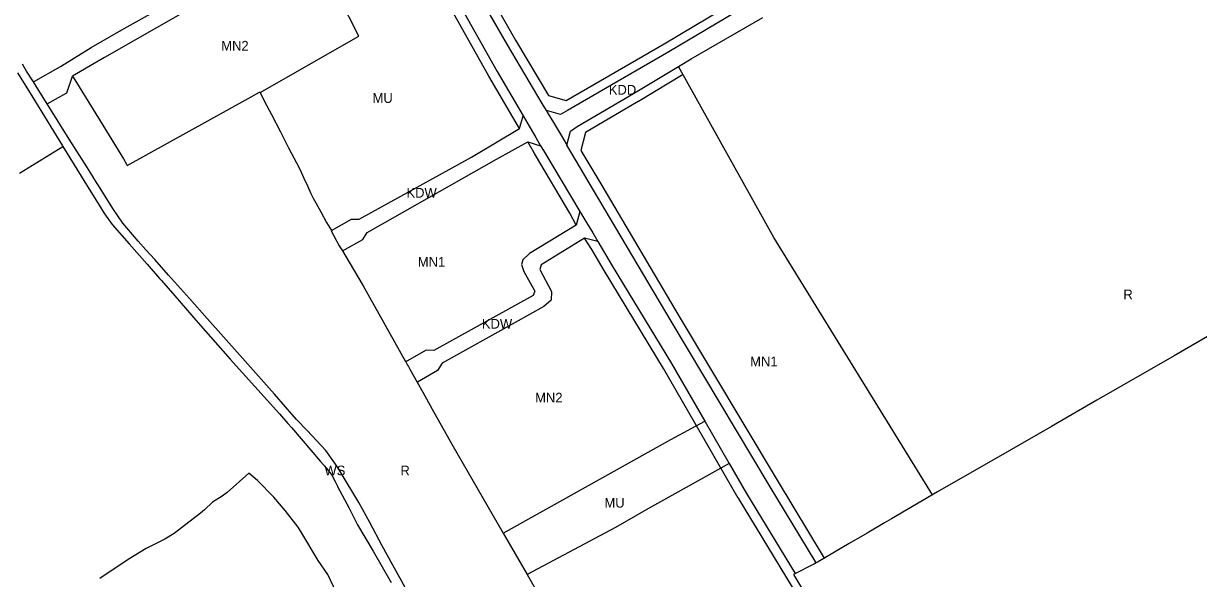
# Model space of a CAD drawing. Extents: x 7435758 to 7439981, y 5550649 to 5554049.
# Drawn here: x 7437442 to 7438071, y 5551241 to 5551538 of the extents above; entities that cross this region are included whole.
import ezdxf

# ---------------------------------------------------------------- set-up
doc = ezdxf.new("R2010")
doc.units = 0
for name, color, linetype in [('#Ruszcza', 7, 'Continuous'), ('linie_rozgraniczające', 7, 'Continuous'), ('linie_zabudowy_nieprzekraczalne', 7, 'Continuous'), ('oznaczenia_przeznaczen', 7, 'Continuous')]:
    doc.layers.add(name, color=color, linetype=linetype)

msp = doc.modelspace()

# ---------------------------------------------------------------- linework, layer by layer
at = {"layer": '#Ruszcza'}
for points in [[(7438090.73, 5551379.13), (7438058.41, 5551360.45), (7438017.13, 5551336.64), (7437992.72, 5551322.56), (7437970.1, 5551309.51), (7437931.84, 5551287.53), (7437907.14, 5551273.07), (7437903.34, 5551270.84), (7437894.03, 5551265.44), (7437884.44, 5551259.9), (7437867.86, 5551250.06), (7437866.85, 5551249.51), (7437865.88, 5551248.94), (7437854.67, 5551243.25), (7437871.03, 5551215.66)], [(7437609.91, 5551233.78), (7437605.33, 5551243.14), (7437600.15, 5551250.74), (7437591.49, 5551265.36), (7437589.42, 5551268.58), (7437582.59, 5551277.49), (7437576.53, 5551284.57), (7437567.78, 5551293.59), (7437563.17, 5551297.51), (7437551.5, 5551287.21), (7437548.85, 5551285.16), (7437543.57, 5551282.06), (7437539.33, 5551277.86), (7437537.17, 5551276.09), (7437523.11, 5551265.13), (7437518.16, 5551262.23), (7437508.19, 5551257.18), (7437498.58, 5551251.32), (7437483.4, 5551241.05)]]:
    msp.add_lwpolyline(points, dxfattribs=at)
at = {"layer": 'linie_rozgraniczające'}
for p, q in [((7437701.57, 5551526.92), (7437651.34, 5551614.85)), ((7437496.28, 5551535.7), (7437578.11, 5551581.52)), ((7437622, 5551531.63), (7437609.34, 5551556.45)), ((7437670.53, 5551558.04), (7437695.96, 5551512.69)), ((7437541.41, 5551552.18), (7437485.75, 5551520.23)), ((7437828.25, 5551547.15), (7437787.93, 5551523.28)), ((7437799.93, 5551519.4), (7437838.31, 5551541.54)), ((7437478.6, 5551525.54), (7437496.28, 5551535.7)), ((7437569.07, 5551501.4), (7437622, 5551531.63)), ((7437464.55, 5551516.73), (7437478.6, 5551525.54)), ((7437720.17, 5551495.53), (7437701.57, 5551526.92)), ((7437482.38, 5551518.3), (7437468.63, 5551510.25)), ((7437485.75, 5551520.23), (7437482.38, 5551518.3)), ((7437787.93, 5551523.28), (7437733.69, 5551491.76)), ((7437793.08, 5551515.29), (7437799.93, 5551519.4)), ((7437439.31, 5551511.91), (7437443.68, 5551504.82)), ((7437444.13, 5551512.88), (7437442, 5551516.56)), ((7437447.8, 5551507.06), (7437444.13, 5551512.88)), ((7437447.87, 5551507.1), (7437462.3, 5551515.43)), ((7437462.3, 5551515.43), (7437464.27, 5551516.57)), ((7437464.27, 5551516.57), (7437464.55, 5551516.73)), ((7437695.96, 5551512.69), (7437709.87, 5551489)), ((7437769.04, 5551500.85), (7437793.08, 5551515.29)), ((7437844.14, 5551423.82), (7437793.08, 5551515.29)), ((7437447.8, 5551507.06), (7437447.87, 5551507.1)), ((7437452.15, 5551500.11), (7437447.8, 5551507.06)), ((7437465.61, 5551501.21), (7437468.63, 5551510.25)), ((7437468.63, 5551510.25), (7437469.93, 5551508.17)), ((7437469.93, 5551508.17), (7437469.93, 5551508.16)), ((7437469.93, 5551508.16), (7437483.59, 5551486.32)), ((7437443.68, 5551504.82), (7437448.84, 5551496.44)), ((7437452.15, 5551500.1), (7437452.15, 5551500.11)), ((7437455.1, 5551495.38), (7437452.15, 5551500.1)), ((7437455.1, 5551495.38), (7437465.61, 5551501.21)), ((7437562.78, 5551498.27), (7437568.83, 5551501.62)), ((7437568.83, 5551501.62), (7437568.93, 5551501.68)), ((7437568.93, 5551501.68), (7437568.96, 5551501.62)), ((7437568.96, 5551501.62), (7437569.07, 5551501.4)), ((7437569.07, 5551501.4), (7437571.51, 5551496.7)), ((7437738.9, 5551483.22), (7437769.04, 5551500.85)), ((7437448.84, 5551496.44), (7437448.85, 5551496.43)), ((7437448.85, 5551496.43), (7437463.41, 5551472.81)), ((7437467.84, 5551475.04), (7437455.1, 5551495.38)), ((7437498, 5551462.41), (7437562.78, 5551498.27)), ((7437571.51, 5551496.7), (7437575.21, 5551489.57)), ((7437722.37, 5551491.81), (7437720.17, 5551495.53)), ((7437575.21, 5551489.57), (7437580.02, 5551480.3)), ((7437708.02, 5551482.1), (7437709.87, 5551489)), ((7437709.87, 5551489), (7437712.39, 5551484.71)), ((7437722.37, 5551491.81), (7437722.89, 5551490.94)), ((7437729.92, 5551489.6), (7437722.37, 5551491.81)), ((7437722.89, 5551490.94), (7437725.29, 5551486.88)), ((7437725.29, 5551486.88), (7437725.68, 5551486.23)), ((7437733.69, 5551491.76), (7437729.92, 5551489.6)), ((7437483.59, 5551486.32), (7437495.92, 5551465.91)), ((7437682.35, 5551466.73), (7437708.02, 5551482.1)), ((7437712.39, 5551484.71), (7437716.73, 5551477.32)), ((7437725.68, 5551486.23), (7437730.4, 5551478.26)), ((7437733.34, 5551473.3), (7437735.26, 5551480.73)), ((7437735.26, 5551480.73), (7437738.9, 5551483.22)), ((7437468.5, 5551473.97), (7437467.84, 5551475.04)), ((7437580.02, 5551480.3), (7437584.4, 5551471.85)), ((7437695.61, 5551465.77), (7437712.43, 5551474.97)), ((7437712.43, 5551474.97), (7437719.31, 5551472.93)), ((7437716.73, 5551477.32), (7437719.31, 5551472.93)), ((7437730.4, 5551478.26), (7437732.96, 5551473.93)), ((7437440.33, 5551458.26), (7437463.55, 5551472.55)), ((7437463.41, 5551472.81), (7437463.56, 5551472.56)), ((7437463.55, 5551472.55), (7437463.56, 5551472.56)), ((7437463.56, 5551472.56), (7437477.15, 5551450.5)), ((7437477.53, 5551459.57), (7437468.5, 5551473.97)), ((7437584.4, 5551471.85), (7437588.57, 5551463.81)), ((7437719.31, 5551472.93), (7437720.79, 5551470.41)), ((7437720.79, 5551470.41), (7437740.34, 5551437.61)), ((7437732.96, 5551473.93), (7437733.34, 5551473.3)), ((7437735.5, 5551469.63), (7437733.34, 5551473.3)), ((7437747.69, 5551449.05), (7437735.5, 5551469.63)), ((7437495.92, 5551465.91), (7437497.67, 5551462.96)), ((7437497.67, 5551462.96), (7437498, 5551462.41)), ((7437588.57, 5551463.81), (7437590.39, 5551460.3)), ((7437622.11, 5551433.49), (7437682.35, 5551466.73)), ((7437628.08, 5551427.37), (7437695.61, 5551465.77)), ((7437481.55, 5551453.16), (7437477.53, 5551459.57)), ((7437590.39, 5551460.3), (7437592.55, 5551455.6)), ((7437592.55, 5551455.6), (7437594.43, 5551451.51)), ((7437477.15, 5551450.5), (7437482.92, 5551441.05)), ((7437482.57, 5551451.53), (7437481.55, 5551453.16)), ((7437490.26, 5551439.33), (7437482.57, 5551451.53)), ((7437594.43, 5551451.51), (7437596.37, 5551447.27)), ((7437789.1, 5551378.96), (7437747.69, 5551449.05)), ((7437596.37, 5551447.27), (7437597.49, 5551444.84)), ((7437597.49, 5551444.84), (7437598.94, 5551442.27)), ((7437482.92, 5551441.05), (7437485.77, 5551436.37)), ((7437485.77, 5551436.37), (7437490, 5551430.8)), ((7437495.56, 5551431.41), (7437490.26, 5551439.33)), ((7437598.94, 5551442.27), (7437601.67, 5551437.43)), ((7437601.67, 5551437.43), (7437604.73, 5551431.76)), ((7437740.34, 5551437.61), (7437738.36, 5551430.44)), ((7437740.34, 5551437.61), (7437742.94, 5551433.25)), ((7437490, 5551430.8), (7437499.01, 5551420.3)), ((7437497.7, 5551428.94), (7437495.56, 5551431.41)), ((7437604.73, 5551431.76), (7437607.27, 5551427.5)), ((7437607.27, 5551427.5), (7437618.01, 5551433.54)), ((7437618.01, 5551433.54), (7437622.11, 5551433.49)), ((7437738.36, 5551430.44), (7437713.37, 5551415.12)), ((7437742.94, 5551433.25), (7437747.16, 5551426.17)), ((7437503.92, 5551421.75), (7437497.7, 5551428.94)), ((7437607.27, 5551427.5), (7437607.08, 5551427.39)), ((7437607.08, 5551427.39), (7437608.34, 5551425.05)), ((7437608.34, 5551425.05), (7437611.46, 5551419.38)), ((7437624.13, 5551422.64), (7437626.4, 5551426.47)), ((7437626.4, 5551426.47), (7437628.08, 5551427.37)), ((7437747.16, 5551426.17), (7437749.88, 5551421.6)), ((7437929.1, 5551285.93), (7437844.14, 5551423.82)), ((7437499.01, 5551420.3), (7437508.62, 5551409.43)), ((7437507.97, 5551417.23), (7437503.92, 5551421.75)), ((7437611.46, 5551419.38), (7437613.22, 5551416.56)), ((7437613.29, 5551416.6), (7437624.13, 5551422.64)), ((7437742.73, 5551423.43), (7437719.6, 5551409.14)), ((7437749.88, 5551421.6), (7437742.73, 5551423.43)), ((7437749.88, 5551421.6), (7437757.63, 5551408.61)), ((7437512.75, 5551411.9), (7437507.97, 5551417.23)), ((7437520.15, 5551403.52), (7437512.75, 5551411.9)), ((7437613.22, 5551416.56), (7437613.29, 5551416.6)), ((7437613.22, 5551416.56), (7437614.54, 5551414.45)), ((7437614.54, 5551414.45), (7437624.22, 5551397.83)), ((7437709.77, 5551411.73), (7437709.12, 5551409.21)), ((7437713.37, 5551415.12), (7437709.77, 5551411.73)), ((7437508.62, 5551409.43), (7437515.35, 5551401.82)), ((7437709.12, 5551409.21), (7437710.27, 5551405.52)), ((7437710.27, 5551405.52), (7437716.18, 5551395.03)), ((7437719.6, 5551409.14), (7437718.96, 5551406.62)), ((7437718.96, 5551406.62), (7437725.17, 5551394.9)), ((7437757.63, 5551408.61), (7437789.38, 5551356.19)), ((7437515.35, 5551401.82), (7437516.3, 5551400.74)), ((7437516.3, 5551400.74), (7437523.48, 5551392.49)), ((7437531.34, 5551390.99), (7437520.15, 5551403.52)), ((7437523.48, 5551392.49), (7437536.04, 5551378.06)), ((7437624.22, 5551397.83), (7437647.01, 5551357.31)), ((7437715.28, 5551392.75), (7437662.21, 5551363.27)), ((7437716.18, 5551395.03), (7437715.28, 5551392.75)), ((7437725.17, 5551394.9), (7437724.86, 5551390.15)), ((7437540.77, 5551380.43), (7437531.34, 5551390.99)), ((7437721.01, 5551386.75), (7437705.65, 5551378.14)), ((7437724.86, 5551390.15), (7437721.01, 5551386.75)), ((7437558.29, 5551360.79), (7437540.77, 5551380.43)), ((7437536.04, 5551378.06), (7437553.16, 5551358.57)), ((7437705.65, 5551378.14), (7437666.54, 5551356.47)), ((7437841.65, 5551291.1), (7437789.1, 5551378.96)), ((7437658.02, 5551363.32), (7437647.67, 5551357.57)), ((7437662.21, 5551363.27), (7437658.02, 5551363.32)), ((7437553.16, 5551358.57), (7437579.45, 5551329.21)), ((7437576.75, 5551339.77), (7437558.29, 5551360.79)), ((7437647.01, 5551357.31), (7437647.06, 5551357.23)), ((7437647.67, 5551357.57), (7437647.06, 5551357.23)), ((7437647.06, 5551357.23), (7437648.08, 5551355.42)), ((7437648.08, 5551355.42), (7437648.55, 5551354.57)), ((7437648.55, 5551354.57), (7437649.32, 5551353.19)), ((7437666.54, 5551356.47), (7437664.13, 5551352.42)), ((7437789.38, 5551356.19), (7437807.13, 5551325.42)), ((7437649.32, 5551353.19), (7437653.21, 5551346.21)), ((7437664.13, 5551352.42), (7437653.43, 5551346.33)), ((7437653.43, 5551346.33), (7437653.21, 5551346.21)), ((7437653.21, 5551346.21), (7437656.2, 5551340.85)), ((7437588.58, 5551326.3), (7437576.75, 5551339.77)), ((7437656.2, 5551340.85), (7437661.21, 5551331.87)), ((7437661.21, 5551331.87), (7437671.69, 5551312.96)), ((7437579.45, 5551329.21), (7437583.99, 5551324.14)), ((7437583.99, 5551324.14), (7437585.86, 5551321.97)), ((7437594.24, 5551320.31), (7437588.58, 5551326.3)), ((7437789.07, 5551315.52), (7437807.13, 5551325.42)), ((7437807.13, 5551325.42), (7437820.24, 5551302.69)), ((7437585.86, 5551321.97), (7437601.54, 5551303.77)), ((7437604.27, 5551309.7), (7437594.24, 5551320.31)), ((7437671.69, 5551312.96), (7437699.26, 5551265.31)), ((7437699.26, 5551265.31), (7437789.07, 5551315.52)), ((7437609.17, 5551302.88), (7437604.27, 5551309.7)), ((7437601.54, 5551303.77), (7437604.53, 5551300.31)), ((7437604.53, 5551300.31), (7437607.51, 5551296.36)), ((7437610.86, 5551300.24), (7437609.17, 5551302.88)), ((7437612.06, 5551298.38), (7437610.86, 5551300.24)), ((7437621.89, 5551281.71), (7437612.06, 5551298.38)), ((7437820.24, 5551302.69), (7437775.73, 5551277.89)), ((7437820.24, 5551302.69), (7437829.46, 5551286.7)), ((7437607.51, 5551296.36), (7437609.23, 5551293.08)), ((7437609.23, 5551293.08), (7437610.55, 5551290.55)), ((7437610.55, 5551290.55), (7437610.6, 5551290.45)), ((7437610.6, 5551290.45), (7437616.72, 5551278.78)), ((7437829.46, 5551286.7), (7437855.59, 5551243.72)), ((7437866.74, 5551249.44), (7437841.65, 5551291.1)), ((7437627.8, 5551271.06), (7437621.89, 5551281.71)), ((7437616.72, 5551278.78), (7437621.18, 5551269.89)), ((7437775.73, 5551277.89), (7437759.38, 5551268.39)), ((7437621.18, 5551269.89), (7437629.59, 5551255.8)), ((7437634.54, 5551258.52), (7437627.8, 5551271.06)), ((7437759.38, 5551268.39), (7437712.09, 5551243.15)), ((7437699.26, 5551265.31), (7437712.09, 5551243.15)), ((7437629.59, 5551255.8), (7437639.26, 5551239)), ((7437646.85, 5551236.19), (7437634.54, 5551258.52)), ((7437712.09, 5551243.15), (7437763.36, 5551154.58))]:
    msp.add_line(p, q, dxfattribs=at)
for points in [[(7438090.73, 5551379.13), (7438058.41, 5551360.45), (7438017.13, 5551336.64), (7437992.72, 5551322.56), (7437970.1, 5551309.51), (7437931.84, 5551287.53), (7437907.14, 5551273.07), (7437903.34, 5551270.84), (7437894.03, 5551265.44), (7437884.44, 5551259.9), (7437867.86, 5551250.06), (7437866.85, 5551249.51), (7437865.88, 5551248.94), (7437854.67, 5551243.25), (7437871.03, 5551215.66)], [(7437609.91, 5551233.78), (7437605.33, 5551243.14), (7437600.15, 5551250.74), (7437591.49, 5551265.36), (7437589.42, 5551268.58), (7437582.59, 5551277.49), (7437576.53, 5551284.57), (7437567.78, 5551293.59), (7437563.17, 5551297.51), (7437551.5, 5551287.21), (7437548.85, 5551285.16), (7437543.57, 5551282.06), (7437539.33, 5551277.86), (7437537.17, 5551276.09), (7437523.11, 5551265.13), (7437518.16, 5551262.23), (7437508.19, 5551257.18), (7437498.58, 5551251.32), (7437483.4, 5551241.05)]]:
    msp.add_lwpolyline(points, dxfattribs=at)
at = {"layer": 'linie_zabudowy_nieprzekraczalne'}
for points in [[(7437653.08, 5551622.16), (7437656.22, 5551616.38), (7437705.89, 5551529.43), (7437723.44, 5551499.81), (7437733, 5551497.15), (7437785.39, 5551527.59), (7437824.77, 5551550.9), (7437825.49, 5551551.92), (7437825.39, 5551552.78), (7437824.87, 5551554.79), (7437810.55, 5551579.2), (7437810.53, 5551579.23), (7437781.56, 5551629.29), (7437756.5, 5551670.46), (7437753.06, 5551676.12)], [(7437708.02, 5551482.1), (7437704.5, 5551488.27), (7437691.65, 5551510.16), (7437691.6, 5551510.25), (7437666.17, 5551555.59), (7437641.24, 5551599.46), (7437637.67, 5551605.66)], [(7437795.66, 5551511), (7437771.62, 5551496.56), (7437771.59, 5551496.55), (7437771.57, 5551496.53), (7437743.24, 5551479.97), (7437740.85, 5551470.41), (7437751.99, 5551451.59), (7437751.99, 5551451.59), (7437793.4, 5551381.52), (7437845.93, 5551293.68), (7437871.06, 5551251.96)], [(7437716.47, 5551467.88), (7437712.43, 5551474.97)], [(7437716.47, 5551467.88), (7437716, 5551468.69)], [(7437738.36, 5551430.44), (7437734.95, 5551436.88), (7437716.49, 5551467.85), (7437716.47, 5551467.88)], [(7437868.08, 5551214), (7437860.28, 5551226.39), (7437860.24, 5551226.45), (7437825.19, 5551284.1), (7437825.13, 5551284.2), (7437785.07, 5551353.65), (7437753.35, 5551406.01), (7437753.34, 5551406.04), (7437746.65, 5551417.27), (7437742.73, 5551423.43)]]:
    msp.add_lwpolyline(points, dxfattribs=at)

# ---------------------------------------------------------------- texts
at = {"layer": 'oznaczenia_przeznaczen'}
for s, p in [('MN2', (7437548.31, 5551523.87)), ('MU', (7437629.33, 5551495.88)), ('KDD', (7437755.79, 5551500.29)), ('KDW', (7437647.47, 5551445.12)), ('MN1', (7437653.56, 5551408.1)), ('R', (7438031.29, 5551390.67)), ('KDW', (7437687.85, 5551374.94)), ('MN1', (7437831.45, 5551354.76)), ('MN2', (7437716.35, 5551335.37)), ('WS', (7437603.57, 5551296.35)), ('R', (7437644.25, 5551296.34)), ('MU', (7437753.46, 5551279.07))]:
    msp.add_text(s, height=5.2, dxfattribs=at).set_placement(p)

doc.saveas('drawing.dxf')
